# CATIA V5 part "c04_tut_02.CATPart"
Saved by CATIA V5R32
Part number: Part1
Bounding box of the stored display mesh (mm): x 0 to 30, y -110 to 110, z -120 to 120
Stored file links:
  D:\PROJECTS\Project 2022\CATIA V5 6R 2022\Resources\Tutorial Files\c04_catia_v5_6r2022_tut\c04_tut_02.CATPart
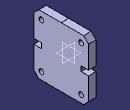
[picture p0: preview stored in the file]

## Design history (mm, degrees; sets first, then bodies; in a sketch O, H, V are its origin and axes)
Body1 (main body)
  Sketch1 on yz-plane, origin (0, 0, 0), H (0, 1, 0), V (0, 0, 1)
    construction line L1 (0, 89.6704) -> (0, 0)
    point P1 (0, 89.6704)
    axis line L2 (0, 0) -> (125.9901, 0)
    point P3 (0, 120)
    line L3 (0, 120) -> (90, 120)
    point P4 (90, 120)
    line L4 (90, 120) -> (110, 100)
    point P5 (110, 100)
    line L5 (110, 100) -> (110, 10)
    point P6 (110, 10)
    line L6 (110, 10) -> (80, 10)
    point P7 (80, 10)
    line L7 (80, 10) -> (80, 0)
    point P8 (80, 0)
    circle A1 centre (80, 90) radius 10
    point P9 (80, 90)
    point P10 (90, -120)
    point P11 (0, -120)
    line L8 (0, -120) -> (90, -120)
    point P12 (110, -100)
    line L9 (90, -120) -> (110, -100)
    point P13 (110, -10)
    line L10 (110, -100) -> (110, -10)
    point P14 (80, -10)
    line L11 (110, -10) -> (80, -10)
    point P15 (80, 0)
    line L12 (80, -10) -> (80, 0)
    circle A2 centre (80, -90) radius 10
    point P17 (-90, 120)
    point P18 (0, 120)
    line L13 (0, 120) -> (-90, 120)
    point P19 (-110, 100)
    line L14 (-90, 120) -> (-110, 100)
    point P20 (-110, 10)
    line L15 (-110, 100) -> (-110, 10)
    circle A3 centre (-80, 90) radius 10
    point P22 (-80, 10)
    line L16 (-110, 10) -> (-80, 10)
    point P23 (-80, 0)
    line L17 (-80, 10) -> (-80, 0)
    point P24 (-80, 0)
    point P25 (-80, -10)
    line L18 (-80, -10) -> (-80, 0)
    point P26 (-110, -10)
    line L19 (-110, -10) -> (-80, -10)
    point P27 (-110, -100)
    line L20 (-110, -100) -> (-110, -10)
    point P28 (-90, -120)
    line L21 (-90, -120) -> (-110, -100)
    circle A4 centre (-80, -90) radius 10
    point P30 (0, -120)
    line L22 (0, -120) -> (-90, -120)
    distance L20 L10 = 220
    distance L3 L8 = 240
    distance L5 P9 = 30
    distance L3 P9 = 30
    radius A1 = 10
    length L14 V = 20
    length L14 H = 20
    distance L6 L11 = 20
    distance L18 L12 = 160
    coincidence: P1 V, P3 L1, P8 L2, P3 P18, P8 P15, P11 P30, P23 P24
    vertical: L1 V, L5 V, L7 V
    horizontal: L2 H, L3 H, L6 H
    symmetry: P4 P10 L2, P3 P11 L2, L3 L8 L2, P5 P12 L2, L4 L9 L2, P6 P13 L2, L5 L10 L2, P7 P14 L2, L6 L11 L2, P8 P15 L2, L7 L12 L2, A1 A2 L2, P4 P17 L1, P3 P18 L1, L3 L13 L1, P5 P19 L1, L4 L14 L1, P6 P20 L1, L5 L15 L1, A1 A3 L1, P7 P22 L1, L6 L16 L1, P8 P23 L1, L7 L17 L1, P15 P24 L1, P14 P25 L1, L12 L18 L1, P13 P26 L1, L11 L19 L1, P12 P27 L1, L10 L20 L1, P10 P28 L1, L9 L21 L1, A2 A4 L1, P11 P30 L1, L8 L22 L1
  Pad1: profile Sketch1, direction (1, 0, 0), length 30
